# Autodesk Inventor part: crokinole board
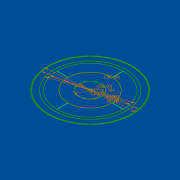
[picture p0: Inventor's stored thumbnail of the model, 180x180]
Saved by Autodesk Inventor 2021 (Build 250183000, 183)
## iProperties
Created: 2020-10
Part Number: crokinole board
Material: Generic
Document SubType Name: Modeling
Designer: Stu
Density: 1 g/cm^3
Appearance: Default
Author: Stu
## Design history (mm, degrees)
sketch "Sketch1" dims "d3" = 609.6, "d4" = 406.4, "d5" = 203.2
  geometry: L1 (-38.881, -93.866)-(0, 0); L2 (0, 0)-(-113.91, 0); L3 (0, -203.2)-(0, -304.8); L4 (203.2, 0)-(304.8, 0); L5 (0, 203.2)-(0, 304.8); L6 (-203.2, 0)-(-304.8, 0); C1 r 387.35 at (0, 0); C2 r 381 at (0, 0); C3 r 330.2 at (0, 0); C4 r 17.463 at (0, 0); C5 r 5 at (-38.881, -93.866); C6 r 5 at (38.881, -93.866); C7 r 5 at (93.866, -38.881); C8 r 5 at (93.866, 38.881); C9 r 5 at (38.881, 93.866); C10 r 5 at (-38.881, 93.866); C11 r 5 at (-93.866, 38.881); C12 r 5 at (-93.866, -38.881); 4 further points
  constraints: 12 centre point, 12 end point, 7 coincident, 2 vertical alignment, 1 horizontal, 1 vertical, 37 other
  dimensions: "d0" = 774.7 diameter of C1; "d1" = 762 diameter of C2; "d2" = 660.4 diameter of C3; "d6" = 34.925 diameter of C4; "d7" = 10 diameter of C5; "d8" = 67.5 deg angle of L2 L1; "d11" = 360 deg dimension on point (0, 0) L1.start (derived); "d15" = 360 deg dimension on point (0, 0) L3.start (derived)
